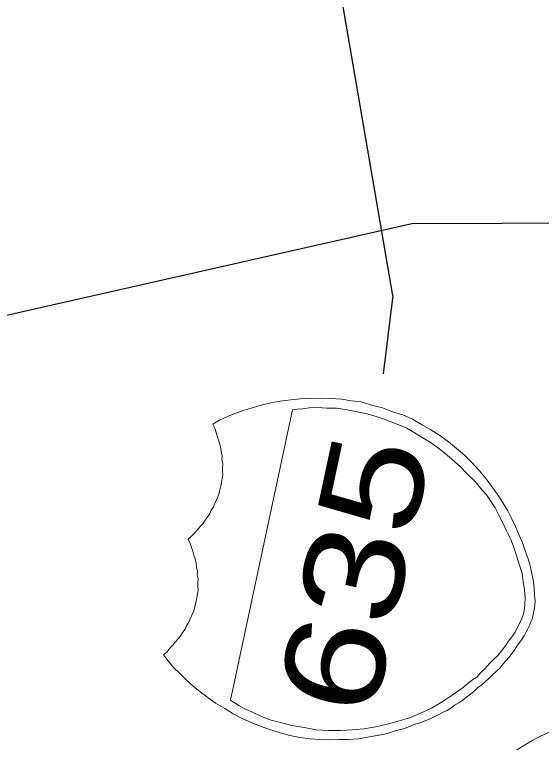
# Model space of a CAD drawing. Extents: x 2363411 to 2369126, y 6976878 to 6988319.
# Drawn here: x 2368214.11 to 2368241.15, y 6988215.22 to 6988252.55 of the extents above; entities that cross this region are included whole.
import ezdxf

# ---------------------------------------------------------------- set-up
doc = ezdxf.new("R2010")
doc.units = 0
doc.header["$LTSCALE"] = 2
doc.layers.add('62', color=7, linetype='Continuous', lineweight=13)
doc.layers.add('63', color=7, linetype='Continuous', lineweight=13)

msp = doc.modelspace()

# ---------------------------------------------------------------- linework, layer by layer
at = {"layer": '62', "lineweight": 25}
msp.add_line((2368233.516, 6988238.138), (2368233.027, 6988234.126), dxfattribs=at)
for points in [[(2368233.516, 6988238.138), (2368228.777, 6988265.707), (2368228.703, 6988266.756)], [(2368213.143, 6988237.017), (2368234.49, 6988241.841), (2368271.473, 6988241.97), (2368300.459, 6988251.424)]]:
    msp.add_lwpolyline(points, dxfattribs=at)
at = {"layer": '62'}
for points in [[(2368223.621, 6988226.288), (2368223.768, 6988226.439), (2368223.898, 6988226.618), (2368223.997, 6988226.758), (2368224.133, 6988226.96), (2368224.192, 6988227.132), (2368224.317, 6988227.289), (2368224.376, 6988227.46), (2368224.464, 6988227.648), (2368224.544, 6988227.815), (2368224.609, 6988228.01), (2368224.647, 6988228.186), (2368224.689, 6988228.382), (2368224.727, 6988228.557), (2368224.769, 6988228.757), (2368224.791, 6988228.961), (2368224.784, 6988229.144), (2368224.773, 6988229.308), (2368224.792, 6988229.511), (2368224.746, 6988229.727), (2368224.762, 6988229.908), (2368224.717, 6988230.124), (2368224.688, 6988230.314), (2368224.637, 6988230.509), (2368224.57, 6988230.732), (2368224.516, 6988230.905), (2368224.447, 6988231.127), (2368224.381, 6988231.347), (2368224.285, 6988231.552), (2368224.629, 6988231.752), (2368225.01, 6988231.927), (2368225.413, 6988232.092), (2368225.862, 6988232.25), (2368226.305, 6988232.386), (2368226.769, 6988232.516), (2368227.257, 6988232.643), (2368227.735, 6988232.725), (2368228.279, 6988232.793), (2368228.772, 6988232.847), (2368229.308, 6988232.871), (2368229.838, 6988232.873), (2368230.362, 6988232.855), (2368230.886, 6988232.833), (2368231.376, 6988232.751), (2368231.891, 6988232.688), (2368232.432, 6988232.525), (2368232.998, 6988232.384), (2368233.507, 6988232.181), (2368234.026, 6988232.025), (2368234.531, 6988231.803), (2368235.021, 6988231.512), (2368235.474, 6988231.255), (2368235.941, 6988230.971), (2368236.379, 6988230.647), (2368236.789, 6988230.306), (2368237.201, 6988229.964), (2368237.58, 6988229.584), (2368237.971, 6988229.157), (2368238.319, 6988228.735), (2368238.641, 6988228.3), (2368238.974, 6988227.814), (2368239.199, 6988227.469), (2368239.419, 6988227.099), (2368239.629, 6988226.686), (2368239.823, 6988226.299), (2368239.992, 6988225.893), (2368240.174, 6988225.465), (2368240.314, 6988225.043), (2368240.459, 6988224.644), (2368240.563, 6988224.278), (2368240.66, 6988223.864), (2368240.741, 6988223.481), (2368240.774, 6988223.104), (2368240.798, 6988222.778), (2368240.818, 6988222.45), (2368240.796, 6988222.132), (2368240.741, 6988221.87)], [(2368240.741, 6988221.87), (2368240.702, 6988221.692), (2368240.669, 6988221.537), (2368240.59, 6988221.37), (2368240.534, 6988221.223), (2368240.451, 6988221.056), (2368240.37, 6988220.889), (2368240.257, 6988220.683), (2368240.148, 6988220.497), (2368240.023, 6988220.344), (2368239.892, 6988220.163), (2368239.759, 6988219.961), (2368239.629, 6988219.784), (2368239.47, 6988219.585), (2368239.344, 6988219.428), (2368239.165, 6988219.237), (2368239.008, 6988219.039), (2368238.836, 6988218.872), (2368238.635, 6988218.683), (2368238.459, 6988218.514), (2368238.284, 6988218.343), (2368238.09, 6988218.18), (2368237.869, 6988218.019), (2368237.697, 6988217.849), (2368237.504, 6988217.704), (2368237.309, 6988217.539), (2368237.116, 6988217.398), (2368236.903, 6988217.258), (2368236.693, 6988217.141), (2368236.497, 6988216.976), (2368236.312, 6988216.854), (2368236.112, 6988216.783), (2368235.876, 6988216.651), (2368235.468, 6988216.46), (2368235.008, 6988216.26), (2368234.538, 6988216.106), (2368234.112, 6988215.944), (2368233.645, 6988215.813), (2368233.175, 6988215.661), (2368232.719, 6988215.575), (2368232.22, 6988215.497), (2368231.742, 6988215.414), (2368231.254, 6988215.379), (2368230.768, 6988215.37), (2368230.282, 6988215.357), (2368229.78, 6988215.375), (2368229.281, 6988215.412), (2368228.743, 6988215.48), (2368228.237, 6988215.588), (2368227.735, 6988215.717), (2368227.26, 6988215.866), (2368226.769, 6988216.04), (2368226.281, 6988216.237), (2368225.798, 6988216.454), (2368225.32, 6988216.694), (2368224.897, 6988216.968), (2368224.423, 6988217.231), (2368224.026, 6988217.526), (2368223.628, 6988217.816), (2368223.257, 6988218.126), (2368222.909, 6988218.43), (2368222.568, 6988218.779), (2368222.265, 6988219.075), (2368221.991, 6988219.409), (2368221.757, 6988219.713), (2368221.926, 6988219.859), (2368222.083, 6988220.058), (2368222.231, 6988220.209), (2368222.353, 6988220.367), (2368222.507, 6988220.54), (2368222.633, 6988220.699), (2368222.742, 6988220.883), (2368222.868, 6988221.04), (2368222.929, 6988221.211), (2368223.059, 6988221.39), (2368223.116, 6988221.562), (2368223.203, 6988221.75), (2368223.288, 6988221.938), (2368223.345, 6988222.087), (2368223.382, 6988222.264), (2368223.429, 6988222.485), (2368223.466, 6988222.661), (2368223.505, 6988222.836), (2368223.524, 6988223.039), (2368223.519, 6988223.226), (2368223.511, 6988223.412), (2368223.534, 6988223.612), (2368223.488, 6988223.828), (2368223.502, 6988224.009), (2368223.451, 6988224.204), (2368223.425, 6988224.396), (2368223.384, 6988224.633), (2368223.31, 6988224.833), (2368223.259, 6988225.028), (2368223.188, 6988225.23), (2368223.114, 6988225.429), (2368223.025, 6988225.653), (2368223.194, 6988225.801), (2368223.342, 6988225.953), (2368223.494, 6988226.127), (2368223.621, 6988226.288)]]:
    msp.add_lwpolyline(points, dxfattribs=at)
msp.add_lwpolyline([(2368228.377, 6988232.287), (2368225.194, 6988217.389), (2368225.396, 6988217.254), (2368225.641, 6988217.11), (2368225.93, 6988216.956), (2368226.328, 6988216.779), (2368226.746, 6988216.573), (2368227.21, 6988216.382), (2368227.755, 6988216.243), (2368228.345, 6988216.096), (2368228.967, 6988215.984), (2368229.587, 6988215.874), (2368230.222, 6988215.83), (2368230.843, 6988215.837), (2368231.448, 6988215.869), (2368232.036, 6988215.927), (2368232.656, 6988216.026), (2368233.236, 6988216.156), (2368233.798, 6988216.312), (2368234.388, 6988216.486), (2368234.948, 6988216.733), (2368235.508, 6988216.981), (2368236.059, 6988217.301), (2368236.572, 6988217.652), (2368237.084, 6988218), (2368237.561, 6988218.406), (2368237.829, 6988218.58), (2368238.039, 6988218.811), (2368238.266, 6988219.014), (2368238.482, 6988219.268), (2368238.689, 6988219.476), (2368238.92, 6988219.702), (2368239.108, 6988219.938), (2368239.298, 6988220.174), (2368239.463, 6988220.415), (2368239.624, 6988220.634), (2368239.791, 6988220.874), (2368239.909, 6988221.103), (2368240.029, 6988221.33), (2368240.118, 6988221.541), (2368240.209, 6988221.75), (2368240.256, 6988221.971), (2368240.3, 6988222.285), (2368240.316, 6988222.674), (2368240.28, 6988223.05), (2368240.21, 6988223.478), (2368240.158, 6988223.88), (2368240.022, 6988224.324), (2368239.882, 6988224.745), (2368239.749, 6988225.188), (2368239.569, 6988225.64), (2368239.362, 6988226.075), (2368239.174, 6988226.483), (2368238.956, 6988226.873), (2368238.764, 6988227.262), (2368238.538, 6988227.609), (2368238.332, 6988227.929), (2368238.104, 6988228.162), (2368237.739, 6988228.61), (2368237.337, 6988228.992), (2368236.98, 6988229.369), (2368236.573, 6988229.732), (2368236.185, 6988230.067), (2368235.811, 6988230.355), (2368235.429, 6988230.621), (2368235.022, 6988230.869), (2368234.616, 6988231.114), (2368234.247, 6988231.334), (2368233.825, 6988231.516), (2368233.423, 6988231.671), (2368233.017, 6988231.825), (2368232.608, 6988231.96), (2368232.195, 6988232.07), (2368231.778, 6988232.16), (2368231.185, 6988232.288), (2368230.625, 6988232.361), (2368230.122, 6988232.374), (2368229.668, 6988232.404), (2368229.225, 6988232.382), (2368228.895, 6988232.338), (2368228.613, 6988232.308)], close=True, dxfattribs=at)
msp.add_circle((2368245.126, 6988207.082), 9.364, dxfattribs=at)
at = {"layer": '63', "lineweight": 25}
msp.add_line((2368233.516, 6988238.138), (2368233.027, 6988234.126), dxfattribs=at)
for points in [[(2368233.516, 6988238.138), (2368228.777, 6988265.707), (2368228.703, 6988266.756)], [(2368213.143, 6988237.017), (2368234.49, 6988241.841), (2368271.473, 6988241.97), (2368300.459, 6988251.424)]]:
    msp.add_lwpolyline(points, dxfattribs=at)
at = {"layer": '63'}
for points in [[(2368223.621, 6988226.288), (2368223.768, 6988226.439), (2368223.898, 6988226.618), (2368223.997, 6988226.758), (2368224.133, 6988226.96), (2368224.192, 6988227.132), (2368224.317, 6988227.289), (2368224.376, 6988227.46), (2368224.464, 6988227.648), (2368224.544, 6988227.815), (2368224.609, 6988228.01), (2368224.647, 6988228.186), (2368224.689, 6988228.382), (2368224.727, 6988228.557), (2368224.769, 6988228.757), (2368224.791, 6988228.961), (2368224.784, 6988229.144), (2368224.773, 6988229.308), (2368224.792, 6988229.511), (2368224.746, 6988229.727), (2368224.762, 6988229.908), (2368224.717, 6988230.124), (2368224.688, 6988230.314), (2368224.637, 6988230.509), (2368224.57, 6988230.732), (2368224.516, 6988230.905), (2368224.447, 6988231.127), (2368224.381, 6988231.347), (2368224.285, 6988231.552), (2368224.629, 6988231.752), (2368225.01, 6988231.927), (2368225.413, 6988232.092), (2368225.862, 6988232.25), (2368226.305, 6988232.386), (2368226.769, 6988232.516), (2368227.257, 6988232.643), (2368227.735, 6988232.725), (2368228.279, 6988232.793), (2368228.772, 6988232.847), (2368229.308, 6988232.871), (2368229.838, 6988232.873), (2368230.362, 6988232.855), (2368230.886, 6988232.833), (2368231.376, 6988232.751), (2368231.891, 6988232.688), (2368232.432, 6988232.525), (2368232.998, 6988232.384), (2368233.507, 6988232.181), (2368234.026, 6988232.025), (2368234.531, 6988231.803), (2368235.021, 6988231.512), (2368235.474, 6988231.255), (2368235.941, 6988230.971), (2368236.379, 6988230.647), (2368236.789, 6988230.306), (2368237.201, 6988229.964), (2368237.58, 6988229.584), (2368237.971, 6988229.157), (2368238.319, 6988228.735), (2368238.641, 6988228.3), (2368238.974, 6988227.814), (2368239.199, 6988227.469), (2368239.419, 6988227.099), (2368239.629, 6988226.686), (2368239.823, 6988226.299), (2368239.992, 6988225.893), (2368240.174, 6988225.465), (2368240.314, 6988225.043), (2368240.459, 6988224.644), (2368240.563, 6988224.278), (2368240.66, 6988223.864), (2368240.741, 6988223.481), (2368240.774, 6988223.104), (2368240.798, 6988222.778), (2368240.818, 6988222.45), (2368240.796, 6988222.132), (2368240.741, 6988221.87)], [(2368240.741, 6988221.87), (2368240.702, 6988221.692), (2368240.669, 6988221.537), (2368240.59, 6988221.37), (2368240.534, 6988221.223), (2368240.451, 6988221.056), (2368240.37, 6988220.889), (2368240.257, 6988220.683), (2368240.148, 6988220.497), (2368240.023, 6988220.344), (2368239.892, 6988220.163), (2368239.759, 6988219.961), (2368239.629, 6988219.784), (2368239.47, 6988219.585), (2368239.344, 6988219.428), (2368239.165, 6988219.237), (2368239.008, 6988219.039), (2368238.836, 6988218.872), (2368238.635, 6988218.683), (2368238.459, 6988218.514), (2368238.284, 6988218.343), (2368238.09, 6988218.18), (2368237.869, 6988218.019), (2368237.697, 6988217.849), (2368237.504, 6988217.704), (2368237.309, 6988217.539), (2368237.116, 6988217.398), (2368236.903, 6988217.258), (2368236.693, 6988217.141), (2368236.497, 6988216.976), (2368236.312, 6988216.854), (2368236.112, 6988216.783), (2368235.876, 6988216.651), (2368235.468, 6988216.46), (2368235.008, 6988216.26), (2368234.538, 6988216.106), (2368234.112, 6988215.944), (2368233.645, 6988215.813), (2368233.175, 6988215.661), (2368232.719, 6988215.575), (2368232.22, 6988215.497), (2368231.742, 6988215.414), (2368231.254, 6988215.379), (2368230.768, 6988215.37), (2368230.282, 6988215.357), (2368229.78, 6988215.375), (2368229.281, 6988215.412), (2368228.743, 6988215.48), (2368228.237, 6988215.588), (2368227.735, 6988215.717), (2368227.26, 6988215.866), (2368226.769, 6988216.04), (2368226.281, 6988216.237), (2368225.798, 6988216.454), (2368225.32, 6988216.694), (2368224.897, 6988216.968), (2368224.423, 6988217.231), (2368224.026, 6988217.526), (2368223.628, 6988217.816), (2368223.257, 6988218.126), (2368222.909, 6988218.43), (2368222.568, 6988218.779), (2368222.265, 6988219.075), (2368221.991, 6988219.409), (2368221.757, 6988219.713), (2368221.926, 6988219.859), (2368222.083, 6988220.058), (2368222.231, 6988220.209), (2368222.353, 6988220.367), (2368222.507, 6988220.54), (2368222.633, 6988220.699), (2368222.742, 6988220.883), (2368222.868, 6988221.04), (2368222.929, 6988221.211), (2368223.059, 6988221.39), (2368223.116, 6988221.562), (2368223.203, 6988221.75), (2368223.288, 6988221.938), (2368223.345, 6988222.087), (2368223.382, 6988222.264), (2368223.429, 6988222.485), (2368223.466, 6988222.661), (2368223.505, 6988222.836), (2368223.524, 6988223.039), (2368223.519, 6988223.226), (2368223.511, 6988223.412), (2368223.534, 6988223.612), (2368223.488, 6988223.828), (2368223.502, 6988224.009), (2368223.451, 6988224.204), (2368223.425, 6988224.396), (2368223.384, 6988224.633), (2368223.31, 6988224.833), (2368223.259, 6988225.028), (2368223.188, 6988225.23), (2368223.114, 6988225.429), (2368223.025, 6988225.653), (2368223.194, 6988225.801), (2368223.342, 6988225.953), (2368223.494, 6988226.127), (2368223.621, 6988226.288)]]:
    msp.add_lwpolyline(points, dxfattribs=at)
msp.add_lwpolyline([(2368228.377, 6988232.287), (2368225.194, 6988217.389), (2368225.396, 6988217.254), (2368225.641, 6988217.11), (2368225.93, 6988216.956), (2368226.328, 6988216.779), (2368226.746, 6988216.573), (2368227.21, 6988216.382), (2368227.755, 6988216.243), (2368228.345, 6988216.096), (2368228.967, 6988215.984), (2368229.587, 6988215.874), (2368230.222, 6988215.83), (2368230.843, 6988215.837), (2368231.448, 6988215.869), (2368232.036, 6988215.927), (2368232.656, 6988216.026), (2368233.236, 6988216.156), (2368233.798, 6988216.312), (2368234.388, 6988216.486), (2368234.948, 6988216.733), (2368235.508, 6988216.981), (2368236.059, 6988217.301), (2368236.572, 6988217.652), (2368237.084, 6988218), (2368237.561, 6988218.406), (2368237.829, 6988218.58), (2368238.039, 6988218.811), (2368238.266, 6988219.014), (2368238.482, 6988219.268), (2368238.689, 6988219.476), (2368238.92, 6988219.702), (2368239.108, 6988219.938), (2368239.298, 6988220.174), (2368239.463, 6988220.415), (2368239.624, 6988220.634), (2368239.791, 6988220.874), (2368239.909, 6988221.103), (2368240.029, 6988221.33), (2368240.118, 6988221.541), (2368240.209, 6988221.75), (2368240.256, 6988221.971), (2368240.3, 6988222.285), (2368240.316, 6988222.674), (2368240.28, 6988223.05), (2368240.21, 6988223.478), (2368240.158, 6988223.88), (2368240.022, 6988224.324), (2368239.882, 6988224.745), (2368239.749, 6988225.188), (2368239.569, 6988225.64), (2368239.362, 6988226.075), (2368239.174, 6988226.483), (2368238.956, 6988226.873), (2368238.764, 6988227.262), (2368238.538, 6988227.609), (2368238.332, 6988227.929), (2368238.104, 6988228.162), (2368237.739, 6988228.61), (2368237.337, 6988228.992), (2368236.98, 6988229.369), (2368236.573, 6988229.732), (2368236.185, 6988230.067), (2368235.811, 6988230.355), (2368235.429, 6988230.621), (2368235.022, 6988230.869), (2368234.616, 6988231.114), (2368234.247, 6988231.334), (2368233.825, 6988231.516), (2368233.423, 6988231.671), (2368233.017, 6988231.825), (2368232.608, 6988231.96), (2368232.195, 6988232.07), (2368231.778, 6988232.16), (2368231.185, 6988232.288), (2368230.625, 6988232.361), (2368230.122, 6988232.374), (2368229.668, 6988232.404), (2368229.225, 6988232.382), (2368228.895, 6988232.338), (2368228.613, 6988232.308)], close=True, dxfattribs=at)
msp.add_circle((2368245.126, 6988207.082), 9.364, dxfattribs=at)

# ---------------------------------------------------------------- texts
at = {"layer": '62', "width": 1.25}
msp.add_text('635', height=5.099, rotation=77.939, dxfattribs=at).set_placement((2368232.545, 6988216.372))
at = {"layer": '63', "width": 1.25}
msp.add_text('635', height=5.099, rotation=77.939, dxfattribs=at).set_placement((2368232.545, 6988216.372))

doc.saveas('drawing.dxf')
